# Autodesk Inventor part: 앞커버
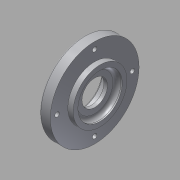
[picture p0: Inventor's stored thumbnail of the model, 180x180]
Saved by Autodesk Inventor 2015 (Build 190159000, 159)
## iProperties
Created: 2015-09
Part Number: 앞커버
Material: 알루미늄 6061
Document SubType Name: Modeling
Designer: mduedu
Density: 1 g/cm^3
Appearance: 알루미늄 - 평지
Author: mduedu
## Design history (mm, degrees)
sketch "스케치1"
  geometry: L1 (-8, 67)-(-12, 67); L2 (-12, 67)-(-12, 80); L3 (-12, 80)-(-20, 80); L4 (-20, 80)-(-20, 70.5); L5 (-23, 70.5)-(-23, 56.5); L6 (-23, 56.5)-(-8, 56.5); L7 (-8, 56.5)-(-8, 67); L8 (-79.5, 39.5)-(-79.5, 54.5) reference; L9 (48.5, 54.5)-(48.5, 39.5) reference; L10 (-79.5, 47)-(48.5, 47); L11 (-20, 70.5)-(-23, 70.5); 3 further points
  constraints: 18 end point, 6 parallel, 4 midpoint, 1 horizontal, 1 perpendicular, 1 vertical alignment
  dimensions: "d0" = 15 distance between parallel lines of L7 L5; "d2" = 19 diameter of L6 L10; "d3" = 40 diameter of L1 L10; "d5" = 4 distance of L1.start L1.end; "d6" = 66 diameter of L3 L10; "d7" = 8 distance of L2.end L3.end; "d8" = 47 diameter of L4.end L10
revolve "회전1" sketch "스케치1" stored, may be unused: angle "d4" = 90 deg
sketch "스케치2"
  geometry: C1 r 33 at (0, 0) reference; 2 further points
  constraints: 1 coincident
hole "구멍1" sketch "스케치2" at (0, 0) diameter "d11" = 33; stored, may be unused: countersink angle "d15" = 90 deg, drill point angle "d17" = 0 deg; dims "d12" = 6, "d13" = 4, "d14" = 2, "d16" = 4
fillet "모깎기1" dims "d18" = 3
fillet "모깎기2" dims "d19" = 1
sketch "스케치3"
  geometry: C1 r 33 at (0, 0) reference; 2 further points
  constraints: 1 coincident
hole "구멍2" sketch "스케치3" at (0, 0) diameter "d20" = 32; stored, may be unused: countersink angle "d24" = 90 deg, drill point angle "d26" = 0 deg; dims "d21" = 6, "d22" = 4, "d23" = 2, "d25" = 8.3
fillet "모깎기3" dims "d27" = 0.3
chamfer "모따기1" distance "d28" = 0.8; stored, may be unused: second distance "d29" = 2, angle "d30" = 30 deg
sketch "스케치4" dims "d31" = 56
  geometry: C1 r 33 at (0, 0) reference; 6 further points
  constraints: 2 vertical alignment, 1 coincident, 7 other
  dimensions: "d36" = 360 deg dimension on C1.centre point (0, 28) (derived)
sketch "스케치7"
  geometry: 4 further points
hole "구멍4" sketch "스케치7" at (0, 28), (-28, 0), (28, 0), (0, -28) diameter "d48" = 3.4; stored, may be unused: countersink angle "d52" = 90 deg, drill point angle "d54" = 0 deg; dims "d49" = 6, "d50" = 6.5, "d51" = 3.4, "d53" = 8
node "솔리드1"
node "참조1"
node "참조2"
